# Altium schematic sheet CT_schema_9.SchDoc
size 209 x 185 mm
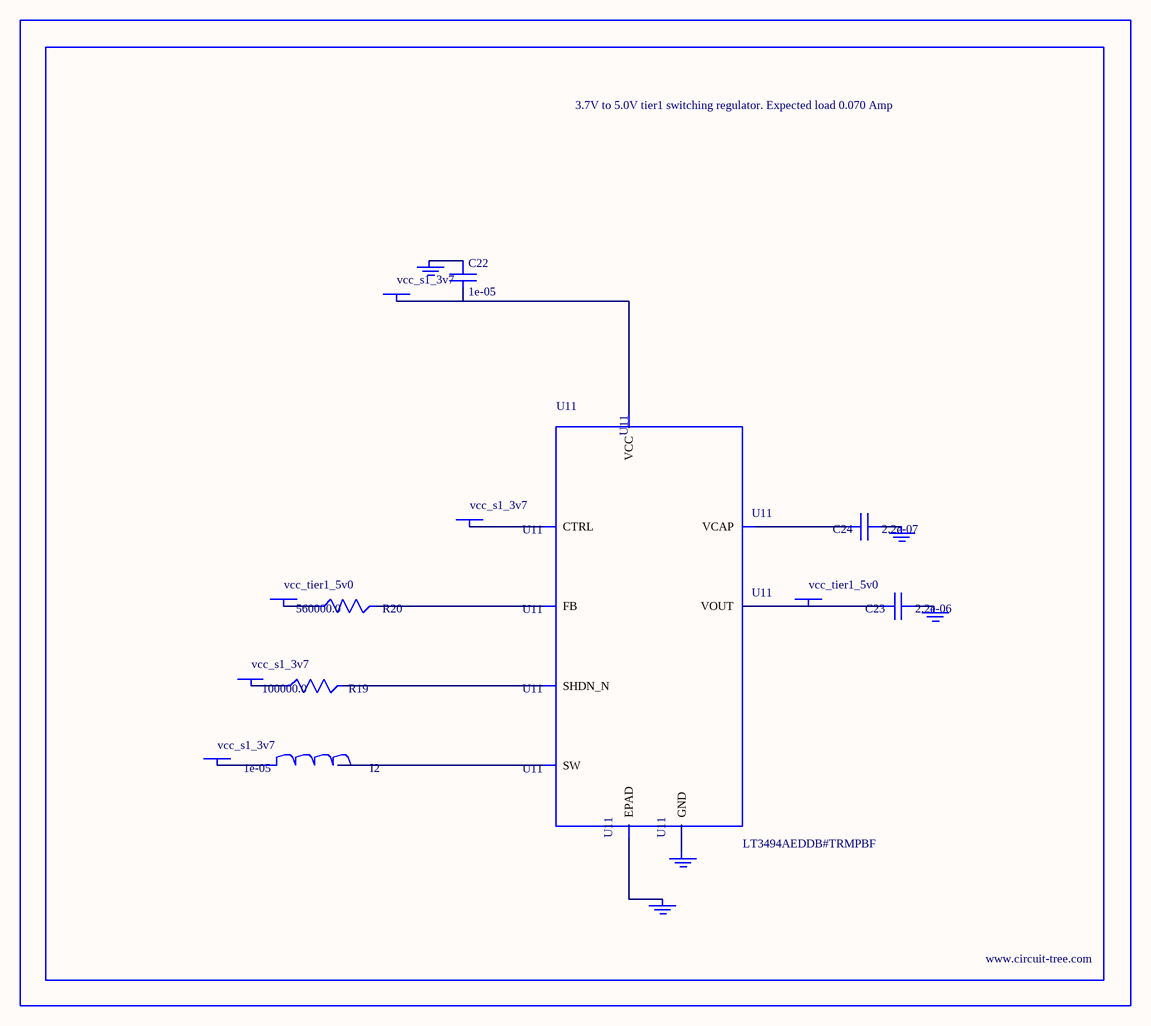
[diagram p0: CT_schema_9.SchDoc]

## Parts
BORDER8  (no value)
C22  1e-05  [C1210]
C23  2.2e-06  [C0603]
C24  2.2e-07  [C0603]
GND_INSTANCE_8_0  (no value)
GND_INSTANCE_8_1  (no value)
GND_INSTANCE_8_2  (no value)
GND_INSTANCE_8_3  (no value)
GND_INSTANCE_8_4  (no value)
I2  1e-05  [L1210]
POWER_INSTANCE_8_0  vcc_s1_3v7
POWER_INSTANCE_8_1  vcc_s1_3v7
POWER_INSTANCE_8_2  vcc_s1_3v7
POWER_INSTANCE_8_3  vcc_s1_3v7
POWER_INSTANCE_8_4  vcc_tier1_5v0
POWER_INSTANCE_8_5  vcc_tier1_5v0
R19  100000.0  [R0603]
R20  560000.0  [R0603]
U11  LT3494AEDDB#TRMPBF  [DFN-8_DDB]

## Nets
NetC22_1: C22.1 GND_INSTANCE_8_0.0(GND)
NetC22_2: C22.2 POWER_INSTANCE_8_1.0(PWR) U11.3(VCC)
NetC23_1: C23.1 GND_INSTANCE_8_1.0(GND)
NetC23_2: C23.2 POWER_INSTANCE_8_5.0(PWR) U11.7(VOUT)
NetC24_1: C24.1 GND_INSTANCE_8_2.0(GND)
NetC24_2: C24.2 U11.8(VCAP)
NetGND_INSTANCE_8_3_0: GND_INSTANCE_8_3.0(GND) U11.9(EPAD)
NetGND_INSTANCE_8_4_0: GND_INSTANCE_8_4.0(GND) U11.2(GND)
NetI2_1: I2.1 POWER_INSTANCE_8_0.0(PWR)
NetI2_2: I2.2 U11.1(SW)
NetPOWER_INSTANCE_8_2_0: POWER_INSTANCE_8_2.0(PWR) U11.4(CTRL)
NetPOWER_INSTANCE_8_3_0: POWER_INSTANCE_8_3.0(PWR) R19.1
NetPOWER_INSTANCE_8_4_0: POWER_INSTANCE_8_4.0(PWR) R20.1
NetR19_2: R19.2 U11.5(SHDN_N)
NetR20_2: R20.2 U11.6(FB)

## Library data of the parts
BORDER8 = BORDER_PAGE8
C22 = C1210C106K5PACTU
C23 = GRM188R61H225KE1115D
C24 = C0603C224K3RAC
GND_INSTANCE_8_0-GND_INSTANCE_8_4 = GND
I2 = CBC3225T100MR
POWER_INSTANCE_8_0-POWER_INSTANCE_8_5 = PWR
R19 = RC0603JR-07100KL
R20 = RC0603JR-07560KL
